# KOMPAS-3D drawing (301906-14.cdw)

Referenced files: лист 3-мешалка.cdw
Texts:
  Мешалка
  денис
  Текст на чертеже
  Размерные надписи
  Шероховатость
  Линия-выноска #1
  Линия-выноска #2
  Линия-выноска #3
  Отклонения формы и база
  Заголовок таблицы
  Ячейка таблицы
  Стрелка вида
  Обозначение изменения
  Фигурная скобка
  Номер узла
  Марка координационной оси
  VRCB
  Выносная надпись
  Обозначение узла
  Марка/позиционное обозначение с линией-выноской
  Марка/позиционное обозначение на линии
  Марка/позиционное обозначение без линии-выноски
  ГОСТ 5632-72-Т6
  Технические требования
  1. После сварки неровности зачистить с плавным переходом к основному металлу.
  2. Сварные швы подлежат контролю качества соединений
  Ступица
  Лопость
  Баранов Д.А
  СПбГТИ(ТУ)
  гр.364
Dimensions and other numbers on the sheet: 105.16.02.00.000СБ; 7; 49,5; 14; 10; 65; 85; 45; 4 отв.; 6; 70; 60; 49,9; 1; 2; 105.16.02.00.001; 105.16.02.00.002; 1:1; 55; 105.16.02.00.000СБ-; 0; 3; 4; 5; 8; 9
